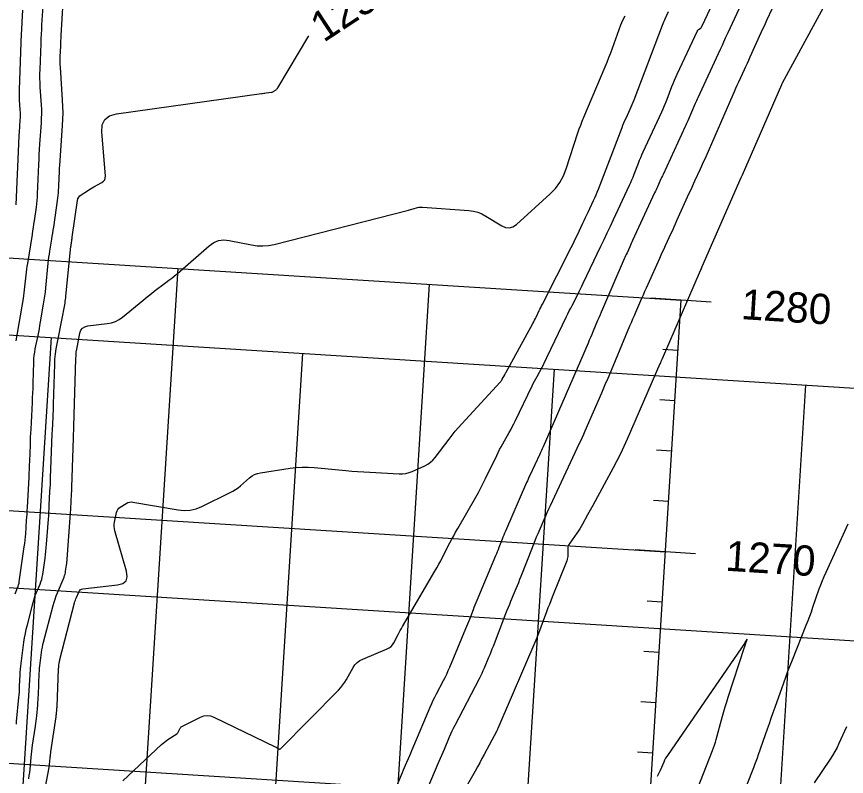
# Model space of a CAD drawing. Extents: x 658976 to 668721, y 639543 to 647196.
# Drawn here: x 661779.9 to 661944.5, y 642005.8 to 642156.5 of the extents above; entities that cross this region are included whole.
import ezdxf

# ---------------------------------------------------------------- set-up
doc = ezdxf.new("R2010")
doc.units = 0
for name, color, linetype in [('Ex_Contour Labels', 7, 'Continuous'), ('Ex_Major Contours', 7, 'Continuous'), ('Ex_Minor Contours', 7, 'Continuous'), ('R_Axis', 7, 'Continuous'), ('R_Axis Annot', 7, 'Continuous'), ('R_Grid', 7, 'Continuous')]:
    doc.layers.add(name, color=color, linetype=linetype)

msp = doc.modelspace()

# ---------------------------------------------------------------- linework, layer by layer
at = {"layer": 'Ex_Major Contours'}
for points in [[(661779.87, 642016.14), (661779.92, 642016.66), (661780.37, 642021.39), (661780.42, 642021.95), (661780.46, 642022.52), (661780.5, 642023.08), (661780.52, 642023.65), (661780.62, 642025.91), (661780.65, 642026.47), (661780.69, 642027.04), (661780.74, 642027.6), (661780.81, 642028.16), (661781.37, 642032.36), (661781.5, 642033.24), (661781.66, 642034.12), (661781.84, 642034.99), (661782.05, 642035.86), (661783.19, 642040.24), (661783.32, 642040.71), (661783.47, 642041.18), (661783.63, 642041.64), (661783.82, 642042.1), (661784.57, 642043.91), (661784.75, 642044.37), (661784.89, 642044.83), (661785.01, 642045.3), (661785.09, 642045.79), (661785.56, 642049.03), (661785.65, 642049.73), (661785.74, 642050.44), (661785.81, 642051.14), (661785.86, 642051.85), (661786.23, 642056.77), (661786.28, 642057.46), (661786.32, 642058.15), (661786.36, 642058.84), (661786.4, 642059.53), (661786.54, 642062.29), (661786.58, 642062.98), (661786.61, 642063.67), (661786.64, 642064.36), (661786.66, 642065.05), (661786.91, 642071.85), (661786.93, 642072.49), (661786.96, 642073.14), (661786.99, 642073.78), (661787.02, 642074.43), (661787.15, 642077.01), (661787.19, 642077.66), (661787.21, 642078.3), (661787.24, 642078.95), (661787.26, 642079.59), (661787.47, 642087.52), (661787.52, 642088.54), (661787.62, 642089.56), (661787.76, 642090.57), (661787.94, 642091.57), (661789.03, 642096.92), (661789.1, 642097.26), (661789.16, 642097.6), (661789.23, 642097.94), (661789.29, 642098.28), (661789.52, 642099.64), (661789.57, 642099.99), (661789.62, 642100.33), (661789.67, 642100.67), (661789.71, 642101.02), (661790.69, 642110.88), (661790.71, 642111.03), (661790.73, 642111.19), (661790.75, 642111.34), (661790.78, 642111.5), (661790.88, 642112.11), (661790.9, 642112.27), (661790.93, 642112.42), (661790.95, 642112.58), (661790.97, 642112.73), (661792.01, 642120), (661792.09, 642120.34), (661792.24, 642120.64), (661792.45, 642120.9), (661792.73, 642121.12), (661793.96, 642121.91), (661794.27, 642122.11), (661794.58, 642122.3), (661794.9, 642122.48), (661795.22, 642122.66), (661796.84, 642123.56), (661797.17, 642123.8), (661797.39, 642124.09), (661797.51, 642124.43), (661797.53, 642124.84), (661796.82, 642133.55), (661796.91, 642134.98), (661797.42, 642136.06), (661798.36, 642136.79), (661799.74, 642137.19), (661828.5, 642141.19), (661828.72, 642141.22), (661828.95, 642141.25), (661829.18, 642141.28), (661829.4, 642141.31), (661830.5, 642141.46), (661830.63, 642141.49), (661830.75, 642141.53), (661830.86, 642141.58), (661830.97, 642141.65), (661831.38, 642141.95), (661831.48, 642142.04), (661831.57, 642142.13), (661831.65, 642142.22), (661831.73, 642142.33), (661837.88, 642152.64)], [(661912.02, 641995.73), (661917.97, 642010.88), (661918.18, 642011.43), (661918.37, 642011.98), (661918.54, 642012.53), (661918.7, 642013.09), (661919.95, 642017.69), (661920.22, 642018.64), (661920.5, 642019.59), (661920.79, 642020.53), (661921.09, 642021.47), (661924.34, 642031.39), (661924.37, 642031.49), (661924.41, 642031.58), (661924.44, 642031.68), (661924.47, 642031.78), (661924.59, 642032.17), (661924.62, 642032.26), (661924.65, 642032.36), (661924.68, 642032.45), (661924.72, 642032.54), (661924.85, 642032.92), (661924.87, 642032.99), (661924.88, 642033.02), (661924.85, 642033), (661924.81, 642032.94), (661924.4, 642032.3), (661924.39, 642032.29), (661924.39, 642032.28), (661924.38, 642032.27), (661924.38, 642032.26), (661924.36, 642032.2), (661924.36, 642032.19), (661924.35, 642032.18), (661924.35, 642032.17), (661924.34, 642032.16), (661909.15, 642010.12), (661908.91, 642009.75), (661908.68, 642009.37), (661908.48, 642008.97), (661908.3, 642008.57), (661907.6, 642006.92), (661907.42, 642006.52), (661907.21, 642006.13), (661906.98, 642005.74)]]:
    msp.add_lwpolyline(points, dxfattribs=at)
at = {"layer": 'Ex_Minor Contours'}
for points in [[(661800.99, 642004.88), (661808.68, 642012.07), (661808.98, 642012.34), (661809.28, 642012.59), (661809.6, 642012.83), (661809.93, 642013.06), (661811.68, 642014.21), (661811.8, 642014.3), (661811.9, 642014.4), (661811.99, 642014.52), (661812.06, 642014.66), (661812.31, 642015.22), (661812.38, 642015.36), (661812.47, 642015.47), (661812.58, 642015.57), (661812.71, 642015.64), (661816.41, 642017.51), (661817.07, 642017.76), (661817.73, 642017.85), (661818.4, 642017.77), (661819.07, 642017.53), (661831.21, 642011.66), (661831.3, 642011.61), (661831.4, 642011.56), (661831.49, 642011.51), (661831.59, 642011.45), (661831.95, 642011.23), (661832.04, 642011.19), (661832.13, 642011.19), (661832.21, 642011.21), (661832.29, 642011.27), (661843.76, 642022.89), (661844.21, 642023.39), (661844.63, 642023.9), (661845.01, 642024.45), (661845.36, 642025.02), (661846.68, 642027.36), (661847.05, 642027.9), (661847.48, 642028.36), (661847.99, 642028.75), (661848.58, 642029.05), (661853.46, 642031.09), (661853.86, 642031.29), (661854.21, 642031.56), (661854.5, 642031.88), (661854.74, 642032.26), (661855.6, 642033.9), (661855.81, 642034.31), (661856.03, 642034.71), (661856.26, 642035.12), (661856.49, 642035.52), (661862.88, 642046.44), (661863.28, 642047.14), (661863.67, 642047.83), (661864.05, 642048.54), (661864.42, 642049.25), (661865.89, 642052.09), (661866.26, 642052.8), (661866.63, 642053.51), (661867.02, 642054.21), (661867.42, 642054.91), (661871, 642061.14), (661871.52, 642062.06), (661872.02, 642062.99), (661872.5, 642063.93), (661872.97, 642064.88), (661875.17, 642069.43), (661875.45, 642070.01), (661875.75, 642070.58), (661876.05, 642071.15), (661876.37, 642071.72), (661877.64, 642073.96), (661877.95, 642074.53), (661878.26, 642075.1), (661878.55, 642075.67), (661878.84, 642076.25), (661882.19, 642083.23), (661882.42, 642083.7), (661882.66, 642084.17), (661882.91, 642084.64), (661883.16, 642085.11), (661884.17, 642086.96), (661884.42, 642087.42), (661884.67, 642087.89), (661884.91, 642088.36), (661885.14, 642088.83), (661889.04, 642096.97), (661889.3, 642097.52), (661889.57, 642098.07), (661889.85, 642098.62), (661890.12, 642099.17), (661891.23, 642101.36), (661891.51, 642101.91), (661891.78, 642102.46), (661892.05, 642103.01), (661892.31, 642103.56), (661895.84, 642110.94), (661896.47, 642112.25), (661897.09, 642113.57), (661897.71, 642114.88), (661898.32, 642116.19), (661901.5, 642123.01), (661901.75, 642123.55), (661901.99, 642124.1), (661902.21, 642124.64), (661902.43, 642125.2), (661903.28, 642127.41), (661903.5, 642127.97), (661903.73, 642128.51), (661903.97, 642129.06), (661904.21, 642129.6), (661907.93, 642137.56), (661908.21, 642138.17), (661908.48, 642138.79), (661908.73, 642139.42), (661908.98, 642140.05), (661909.94, 642142.57), (661910.18, 642143.2), (661910.44, 642143.83), (661910.71, 642144.45), (661910.99, 642145.06), (661914.99, 642153.62), (661915.03, 642153.7), (661915.08, 642153.76), (661915.14, 642153.82), (661915.21, 642153.86), (661915.54, 642154.06), (661915.59, 642154.09), (661915.64, 642154.13), (661915.67, 642154.18), (661915.71, 642154.23), (661915.82, 642154.43), (661915.85, 642154.49), (661915.88, 642154.54), (661915.91, 642154.59), (661915.93, 642154.65), (661920.21, 642163.81)], [(661925.45, 642162.82), (661921.03, 642153.26), (661920.9, 642152.98), (661920.77, 642152.71), (661920.64, 642152.43), (661920.52, 642152.15), (661920.01, 642151.03), (661919.89, 642150.75), (661919.76, 642150.47), (661919.63, 642150.19), (661919.5, 642149.91), (661915.07, 642140.33), (661914.94, 642140.05), (661914.81, 642139.77), (661914.68, 642139.48), (661914.56, 642139.2), (661913.07, 642135.79), (661912.94, 642135.5), (661912.82, 642135.22), (661912.69, 642134.93), (661912.56, 642134.65), (661908.17, 642125.17), (661908.03, 642124.86), (661907.89, 642124.56), (661907.75, 642124.25), (661907.61, 642123.94), (661907.06, 642122.72), (661906.92, 642122.41), (661906.78, 642122.11), (661906.64, 642121.8), (661906.5, 642121.5), (661902.12, 642112.04), (661901.98, 642111.73), (661901.84, 642111.43), (661901.7, 642111.13), (661901.57, 642110.82), (661901.02, 642109.6), (661900.88, 642109.3), (661900.75, 642109), (661900.61, 642108.69), (661900.48, 642108.38), (661896.14, 642098.4), (661895.9, 642097.84), (661895.66, 642097.29), (661895.43, 642096.73), (661895.19, 642096.17), (661894.25, 642093.94), (661894.02, 642093.39), (661893.78, 642092.83), (661893.54, 642092.27), (661893.3, 642091.72), (661884.36, 642071.11), (661884.2, 642070.74), (661884.03, 642070.37), (661883.87, 642070.01), (661883.7, 642069.65), (661881.72, 642065.43), (661881.56, 642065.09), (661881.41, 642064.75), (661881.25, 642064.41), (661881.1, 642064.07), (661876.91, 642054.42), (661876.73, 642054.01), (661876.56, 642053.61), (661876.4, 642053.2), (661876.24, 642052.79), (661875.6, 642051.14), (661875.44, 642050.73), (661875.27, 642050.32), (661875.11, 642049.91), (661874.94, 642049.51), (661871.23, 642040.67), (661871.04, 642040.21), (661870.85, 642039.74), (661870.66, 642039.27), (661870.48, 642038.8), (661869.75, 642036.92), (661869.57, 642036.45), (661869.38, 642035.99), (661869.19, 642035.52), (661869, 642035.05), (661865.77, 642027.35), (661865.48, 642026.68), (661865.18, 642026.01), (661864.86, 642025.35), (661864.53, 642024.7), (661863.17, 642022.11), (661862.84, 642021.45), (661862.52, 642020.8), (661862.22, 642020.13), (661861.93, 642019.46), (661858.68, 642011.78), (661858.48, 642011.3), (661858.27, 642010.82), (661858.07, 642010.34), (661857.86, 642009.86), (661857.03, 642007.95), (661856.83, 642007.47), (661856.62, 642006.99), (661856.42, 642006.51), (661856.22, 642006.03), (661852.96, 641998.34)], [(661779.62, 642042), (661780.11, 642043.17), (661780.22, 642043.47), (661780.31, 642043.77), (661780.39, 642044.07), (661780.44, 642044.38), (661781.44, 642051.31), (661781.52, 642051.96), (661781.6, 642052.6), (661781.66, 642053.25), (661781.72, 642053.9), (661781.91, 642056.5), (661781.96, 642057.15), (661782, 642057.8), (661782.04, 642058.45), (661782.07, 642059.1), (661782.39, 642065.14), (661782.43, 642065.93), (661782.46, 642066.72), (661782.49, 642067.51), (661782.52, 642068.3), (661782.64, 642071.46), (661782.67, 642072.25), (661782.7, 642073.04), (661782.74, 642073.83), (661782.78, 642074.62), (661783.05, 642079.94), (661783.1, 642080.87), (661783.14, 642081.8), (661783.17, 642082.73), (661783.2, 642083.66), (661783.32, 642087.89), (661783.35, 642088.57), (661783.41, 642089.24), (661783.5, 642089.91), (661783.62, 642090.57), (661784.17, 642093.22), (661784.3, 642093.89), (661784.43, 642094.55), (661784.55, 642095.22), (661784.66, 642095.89), (661785.27, 642099.4), (661785.4, 642100.21), (661785.51, 642101.02), (661785.62, 642101.83), (661785.71, 642102.64), (661786.2, 642107.57), (661786.27, 642108.17), (661786.34, 642108.77), (661786.42, 642109.36), (661786.52, 642109.95), (661786.9, 642112.33), (661787, 642112.92), (661787.09, 642113.51), (661787.18, 642114.11), (661787.27, 642114.7), (661788.08, 642120.42), (661788.15, 642120.96), (661788.21, 642121.5), (661788.25, 642122.05), (661788.28, 642122.59), (661788.37, 642124.77), (661788.4, 642125.31), (661788.42, 642125.86), (661788.45, 642126.4), (661788.49, 642126.95), (661789.03, 642134.86), (661789.1, 642136.13), (661789.12, 642137.39), (661789.11, 642138.65), (661789.04, 642139.91), (661788.62, 642146.45), (661788.59, 642146.96), (661788.58, 642147.48), (661788.58, 642148), (661788.59, 642148.52), (661788.67, 642150.6), (661788.69, 642151.12), (661788.72, 642151.64), (661788.74, 642152.16), (661788.77, 642152.68), (661789.17, 642159.34)], [(661940.78, 642159.84), (661931.8, 642143.23), (661931.76, 642143.15), (661931.72, 642143.08), (661931.69, 642143.01), (661931.66, 642142.94), (661923.85, 642125.01), (661923.79, 642124.88), (661923.73, 642124.75), (661923.68, 642124.61), (661923.62, 642124.48), (661915.87, 642106.81), (661915.79, 642106.62), (661915.71, 642106.43), (661915.62, 642106.24), (661915.54, 642106.04), (661907.98, 642088.58), (661907.87, 642088.32), (661907.76, 642088.07), (661907.65, 642087.82), (661907.54, 642087.57), (661901.04, 642072.65), (661900.39, 642071.2), (661899.71, 642069.77), (661899, 642068.34), (661898.26, 642066.94), (661894.22, 642059.47), (661893.97, 642059.01), (661893.72, 642058.55), (661893.46, 642058.09), (661893.21, 642057.63), (661892.18, 642055.78), (661891.92, 642055.34), (661891.66, 642054.9), (661891.37, 642054.47), (661891.08, 642054.04), (661889.64, 642052.02), (661889.48, 642051.77), (661889.37, 642051.5), (661889.3, 642051.22), (661889.28, 642050.92), (661889.28, 642049.71), (661889.26, 642049.4), (661889.22, 642049.11), (661889.15, 642048.82), (661889.05, 642048.53), (661886.18, 642041.33), (661885.9, 642040.61), (661885.62, 642039.89), (661885.34, 642039.17), (661885.07, 642038.44), (661883.25, 642033.59), (661883.22, 642033.51), (661883.18, 642033.42), (661883.15, 642033.34), (661883.11, 642033.25), (661875.4, 642015.28), (661875.35, 642015.16), (661875.29, 642015.04), (661875.24, 642014.92), (661875.17, 642014.8), (661872.67, 642010.11), (661872.23, 642009.29), (661871.79, 642008.47), (661871.34, 642007.66), (661870.88, 642006.84), (661868.34, 642002.31)], [(661779.82, 642092.16), (661781.25, 642100.55), (661781.35, 642101.12), (661781.43, 642101.7), (661781.5, 642102.28), (661781.57, 642102.86), (661781.8, 642105.19), (661781.86, 642105.77), (661781.93, 642106.35), (661782.02, 642106.92), (661782.11, 642107.5), (661783.05, 642113.27), (661783.16, 642113.94), (661783.26, 642114.6), (661783.36, 642115.27), (661783.46, 642115.94), (661783.84, 642118.63), (661783.93, 642119.3), (661784, 642119.97), (661784.05, 642120.65), (661784.09, 642121.32), (661784.32, 642127.09), (661784.37, 642128.1), (661784.42, 642129.1), (661784.48, 642130.11), (661784.54, 642131.12), (661784.84, 642135.4), (661784.88, 642136.28), (661784.9, 642137.16), (661784.89, 642138.04), (661784.84, 642138.92), (661784.62, 642142.45), (661784.57, 642143.33), (661784.55, 642144.21), (661784.55, 642145.1), (661784.57, 642145.98), (661784.76, 642151.12), (661784.8, 642152.05), (661784.84, 642152.97), (661784.89, 642153.9), (661784.94, 642154.82), (661785.16, 642158.53)], [(661779.86, 642119.13), (661780.35, 642131.21), (661780.37, 642131.78), (661780.4, 642132.35), (661780.44, 642132.92), (661780.47, 642133.5), (661780.64, 642135.93), (661780.67, 642136.43), (661780.68, 642136.93), (661780.67, 642137.43), (661780.65, 642137.93), (661780.52, 642139.94), (661780.49, 642140.44), (661780.48, 642140.94), (661780.48, 642141.44), (661780.49, 642141.95), (661780.91, 642153.17), (661780.94, 642153.74), (661780.96, 642154.31), (661780.99, 642154.87), (661781.02, 642155.44), (661781.16, 642157.72)], [(661783.94, 641994.72), (661786.35, 642007.56), (661786.4, 642007.82), (661786.44, 642008.08), (661786.47, 642008.33), (661786.5, 642008.59), (661786.59, 642009.62), (661786.62, 642009.88), (661786.65, 642010.14), (661786.68, 642010.4), (661786.72, 642010.65), (661787.74, 642017.57), (661787.77, 642017.74), (661787.79, 642017.92), (661787.81, 642018.1), (661787.83, 642018.27), (661787.89, 642018.98), (661787.91, 642019.16), (661787.92, 642019.33), (661787.93, 642019.51), (661787.94, 642019.69), (661788.24, 642027.06), (661788.25, 642027.22), (661788.26, 642027.38), (661788.28, 642027.54), (661788.3, 642027.7), (661788.38, 642028.33), (661788.41, 642028.49), (661788.43, 642028.65), (661788.47, 642028.81), (661788.51, 642028.96), (661791.42, 642040.17), (661791.49, 642040.45), (661791.58, 642040.73), (661791.68, 642041), (661791.79, 642041.27), (661792.24, 642042.34), (661792.37, 642042.58), (661792.55, 642042.76), (661792.77, 642042.88), (661793.04, 642042.94), (661799.94, 642043.74), (661800.98, 642044.02), (661801.63, 642044.56), (661801.88, 642045.37), (661801.74, 642046.44), (661799.42, 642054.49), (661799.33, 642054.91), (661799.29, 642055.34), (661799.29, 642055.77), (661799.36, 642056.2), (661799.75, 642058.11), (661799.85, 642058.43), (661800, 642058.71), (661800.21, 642058.96), (661800.48, 642059.16), (661801.67, 642059.9), (661801.98, 642060.06), (661802.29, 642060.15), (661802.62, 642060.19), (661802.96, 642060.16), (661811.94, 642058.62), (661813.16, 642058.51), (661814.35, 642058.58), (661815.52, 642058.85), (661816.66, 642059.3), (661822.31, 642062.06), (661822.84, 642062.35), (661823.36, 642062.66), (661823.85, 642063.01), (661824.32, 642063.4), (661826.15, 642065), (661826.63, 642065.36), (661827.14, 642065.64), (661827.69, 642065.85), (661828.27, 642065.98), (661834.21, 642066.87), (661835.4, 642067.01), (661836.59, 642067.08), (661837.78, 642067.08), (661838.98, 642067.01), (661845.2, 642066.43), (661846.39, 642066.33), (661847.58, 642066.23), (661848.78, 642066.15), (661849.98, 642066.08), (661855.8, 642065.77), (661856.47, 642065.77), (661857.13, 642065.85), (661857.78, 642066.01), (661858.4, 642066.25), (661860.89, 642067.37), (661861.49, 642067.68), (661862.03, 642068.06), (661862.52, 642068.51), (661862.95, 642069.02), (661865.71, 642072.68), (661866.32, 642073.46), (661866.94, 642074.23), (661867.59, 642074.98), (661868.25, 642075.72), (661875.83, 642083.94), (661875.96, 642084.08), (661876.07, 642084.22), (661876.18, 642084.38), (661876.27, 642084.54), (661876.78, 642085.43), (661876.8, 642085.47), (661876.82, 642085.51), (661876.84, 642085.55), (661876.86, 642085.59), (661876.94, 642085.76), (661876.96, 642085.8), (661876.98, 642085.84), (661877.01, 642085.88), (661877.03, 642085.92), (661882.35, 642095.61), (661882.52, 642095.92), (661882.68, 642096.23), (661882.84, 642096.55), (661882.99, 642096.86), (661883.6, 642098.14), (661883.75, 642098.45), (661883.91, 642098.77), (661884.07, 642099.08), (661884.22, 642099.4), (661889.94, 642110.68), (661890.24, 642111.26), (661890.53, 642111.85), (661890.81, 642112.44), (661891.1, 642113.03), (661892.26, 642115.47), (661892.53, 642116.02), (661892.8, 642116.58), (661893.06, 642117.14), (661893.32, 642117.7), (661894.37, 642119.95), (661894.62, 642120.51), (661894.87, 642121.08), (661895.11, 642121.65), (661895.33, 642122.22), (661900.04, 642134.44), (661900.22, 642134.91), (661900.41, 642135.37), (661900.61, 642135.82), (661900.82, 642136.28), (661901.66, 642138.08), (661901.87, 642138.54), (661902.06, 642139), (661902.25, 642139.46), (661902.43, 642139.92), (661908.05, 642154.73), (661908.18, 642155.06), (661908.32, 642155.39), (661908.46, 642155.71), (661908.6, 642156.03), (661909.26, 642157.44)], [(661929.81, 642158.06), (661928.69, 642155.65), (661928.41, 642155.04), (661928.14, 642154.44), (661927.86, 642153.84), (661927.59, 642153.23), (661925.4, 642148.38), (661925.12, 642147.76), (661924.84, 642147.14), (661924.55, 642146.52), (661924.27, 642145.9), (661923.12, 642143.42), (661922.83, 642142.8), (661922.55, 642142.18), (661922.27, 642141.55), (661922, 642140.93), (661916.63, 642128.64), (661916.36, 642128.03), (661916.09, 642127.42), (661915.81, 642126.81), (661915.53, 642126.21), (661914.41, 642123.79), (661914.14, 642123.19), (661913.86, 642122.58), (661913.58, 642121.97), (661913.31, 642121.37), (661910.86, 642115.92), (661910.58, 642115.3), (661910.3, 642114.68), (661910.02, 642114.06), (661909.73, 642113.45), (661908.59, 642110.98), (661908.3, 642110.36), (661908.02, 642109.74), (661907.74, 642109.12), (661907.46, 642108.5), (661905.12, 642103.31), (661904.81, 642102.62), (661904.51, 642101.93), (661904.21, 642101.24), (661903.91, 642100.56), (661902.71, 642097.8), (661902.41, 642097.11), (661902.11, 642096.42), (661901.82, 642095.72), (661901.53, 642095.03), (661897.06, 642084.38), (661896.78, 642083.74), (661896.51, 642083.09), (661896.23, 642082.44), (661895.95, 642081.8), (661892.66, 642074.22), (661892.39, 642073.6), (661892.12, 642072.99), (661891.84, 642072.38), (661891.55, 642071.76), (661885.77, 642059.42), (661885.45, 642058.74), (661885.13, 642058.05), (661884.82, 642057.36), (661884.52, 642056.67), (661883.31, 642053.9), (661883.02, 642053.21), (661882.73, 642052.51), (661882.44, 642051.81), (661882.17, 642051.1), (661879.97, 642045.44), (661879.72, 642044.81), (661879.48, 642044.19), (661879.22, 642043.57), (661878.97, 642042.96), (661877.93, 642040.49), (661877.68, 642039.88), (661877.43, 642039.26), (661877.18, 642038.64), (661876.94, 642038.02), (661874.43, 642031.53), (661874.22, 642030.98), (661874, 642030.44), (661873.78, 642029.9), (661873.56, 642029.37), (661872.66, 642027.22), (661872.43, 642026.68), (661872.19, 642026.15), (661871.94, 642025.63), (661871.67, 642025.11), (661866.85, 642015.88), (661866.55, 642015.3), (661866.27, 642014.71), (661865.99, 642014.12), (661865.73, 642013.52), (661864.72, 642011.12), (661864.46, 642010.52), (661864.21, 642009.92), (661863.95, 642009.32), (661863.69, 642008.72), (661861.27, 642003.11)], [(661782.35, 642005.31), (661782.44, 642005.92), (661782.52, 642006.52), (661782.58, 642007.13), (661782.81, 642009.56), (661782.87, 642010.17), (661782.94, 642010.78), (661783.02, 642011.39), (661783.1, 642011.99), (661783.65, 642015.73), (661783.73, 642016.25), (661783.79, 642016.77), (661783.85, 642017.28), (661783.91, 642017.8), (661784.1, 642019.88), (661784.15, 642020.4), (661784.19, 642020.93), (661784.22, 642021.45), (661784.24, 642021.97), (661784.42, 642026.16), (661784.44, 642026.68), (661784.48, 642027.21), (661784.53, 642027.73), (661784.6, 642028.25), (661784.88, 642030.34), (661784.95, 642030.87), (661785.05, 642031.38), (661785.15, 642031.9), (661785.28, 642032.41), (661787.17, 642039.68), (661787.34, 642040.32), (661787.54, 642040.95), (661787.77, 642041.57), (661788.01, 642042.19), (661789.32, 642045.31), (661789.43, 642045.6), (661789.52, 642045.88), (661789.59, 642046.17), (661789.64, 642046.47), (661789.81, 642047.67), (661789.85, 642047.97), (661789.89, 642048.27), (661789.92, 642048.57), (661789.94, 642048.87), (661790.61, 642057.98), (661790.63, 642058.24), (661790.65, 642058.5), (661790.66, 642058.77), (661790.68, 642059.03), (661790.73, 642060.09), (661790.75, 642060.35), (661790.76, 642060.62), (661790.77, 642060.88), (661790.78, 642061.15), (661791.2, 642072.84), (661791.2, 642073.04), (661791.21, 642073.24), (661791.22, 642073.43), (661791.23, 642073.63), (661791.27, 642074.41), (661791.28, 642074.61), (661791.29, 642074.8), (661791.3, 642075), (661791.3, 642075.2), (661791.67, 642088.6), (661791.7, 642089.24), (661791.76, 642089.88), (661791.85, 642090.52), (661791.97, 642091.15), (661792.48, 642093.68), (661792.67, 642094.25), (661792.99, 642094.67), (661793.44, 642094.95), (661794.02, 642095.1), (661797.89, 642095.56), (661798.73, 642095.71), (661799.51, 642095.98), (661800.25, 642096.37), (661800.94, 642096.86), (661804.95, 642100.18), (661805.51, 642100.64), (661806.08, 642101.09), (661806.65, 642101.54), (661807.23, 642101.97), (661809.55, 642103.71), (661810.13, 642104.15), (661810.7, 642104.6), (661811.26, 642105.06), (661811.81, 642105.53), (661818.13, 642111.02), (661819.02, 642111.65), (661819.98, 642112.03), (661821, 642112.17), (661822.09, 642112.07), (661826.55, 642111.16), (661827.67, 642111), (661828.78, 642110.96), (661829.89, 642111.06), (661830.99, 642111.27), (661857.64, 642118.09), (661857.87, 642118.15), (661858.1, 642118.21), (661858.33, 642118.27), (661858.56, 642118.33), (661859.48, 642118.59), (661859.71, 642118.64), (661859.94, 642118.67), (661860.17, 642118.68), (661860.41, 642118.68), (661869.65, 642118), (661870.54, 642117.88), (661871.41, 642117.66), (661872.24, 642117.33), (661873.03, 642116.9), (661876.15, 642114.96), (661876.92, 642114.62), (661877.66, 642114.54), (661878.38, 642114.75), (661879.07, 642115.23), (661885.75, 642121.3), (661886.8, 642122.38), (661887.68, 642123.57), (661888.4, 642124.86), (661888.96, 642126.26), (661891.28, 642133.39), (661891.55, 642134.17), (661891.83, 642134.95), (661892.13, 642135.72), (661892.44, 642136.49), (661896.7, 642146.5), (661897.08, 642147.41), (661897.44, 642148.32), (661897.79, 642149.25), (661898.12, 642150.17), (661899.43, 642153.92), (661899.78, 642154.84), (661900.19, 642155.74), (661900.64, 642156.61)], [(661923.29, 642000.21), (661926.15, 642007.51), (661926.4, 642008.15), (661926.64, 642008.79), (661926.88, 642009.44), (661927.11, 642010.09), (661928.89, 642015.21), (661929.27, 642016.28), (661929.64, 642017.35), (661930.02, 642018.42), (661930.39, 642019.49), (661932.1, 642024.31), (661932.52, 642025.47), (661932.95, 642026.62), (661933.38, 642027.77), (661933.84, 642028.91), (661936.58, 642035.78), (661936.93, 642036.66), (661937.26, 642037.54), (661937.59, 642038.42), (661937.9, 642039.31), (661939.17, 642042.95), (661939.47, 642043.79), (661939.8, 642044.62), (661940.14, 642045.44), (661940.5, 642046.26), (661944.88, 642055.89)], [(661944.58, 642015.59), (661943.07, 642012.31), (661942.68, 642011.49), (661942.25, 642010.7), (661941.8, 642009.92), (661941.31, 642009.17), (661938.14, 642004.48)]]:
    msp.add_lwpolyline(points, dxfattribs=at)
at = {"layer": 'R_Axis'}
for p, q in [((661899.22, 641900.61), (661911.75, 642100.21)), ((661917.74, 642099.84), (661905.77, 642100.59)), ((661911.13, 642090.23), (661908.13, 642090.42)), ((661910.5, 642080.25), (661907.51, 642080.44)), ((661909.87, 642070.27), (661906.88, 642070.46)), ((661909.25, 642060.29), (661906.25, 642060.48)), ((661914.61, 642049.94), (661902.63, 642050.69)), ((661907.99, 642040.33), (661905, 642040.52)), ((661907.37, 642030.35), (661904.37, 642030.54)), ((661906.74, 642020.37), (661903.75, 642020.56)), ((661906.11, 642010.39), (661903.12, 642010.58))]:
    msp.add_line(p, q, dxfattribs=at)
at = {"layer": 'R_Grid'}
for p, q in [((660414.7, 642194.23), (661911.75, 642100.21)), ((660411.57, 642144.33), (661908.62, 642050.31)), ((661799.41, 641906.87), (661811.95, 642106.48)), ((661849.32, 641903.74), (661861.85, 642103.35)), ((661637.1, 642102.2), (663134.15, 642008.18)), ((661899.22, 641900.61), (661911.75, 642100.21)), ((660408.44, 642094.43), (661905.49, 642000.41)), ((661771.13, 641843.29), (661786.81, 642092.79)), ((661821.04, 641840.15), (661836.71, 642089.66)), ((661870.94, 641837.02), (661886.61, 642086.53)), ((661920.84, 641833.88), (661936.51, 642083.39)), ((661633.97, 642052.3), (663131.02, 641958.27))]:
    msp.add_line(p, q, dxfattribs=at)

# ---------------------------------------------------------------- texts
at = {"layer": 'Ex_Contour Labels'}
msp.add_text('1255', height=6, rotation=33.3111, dxfattribs=at).set_placement((661840.82, 642151.21))
at = {"layer": 'R_Axis Annot'}
for s, p in [('1280', (661923.54, 642096.47)), ('1270', (661920.41, 642046.57))]:
    msp.add_text(s, height=6, rotation=356.4063, dxfattribs=at).set_placement(p)

doc.saveas('drawing.dxf')
